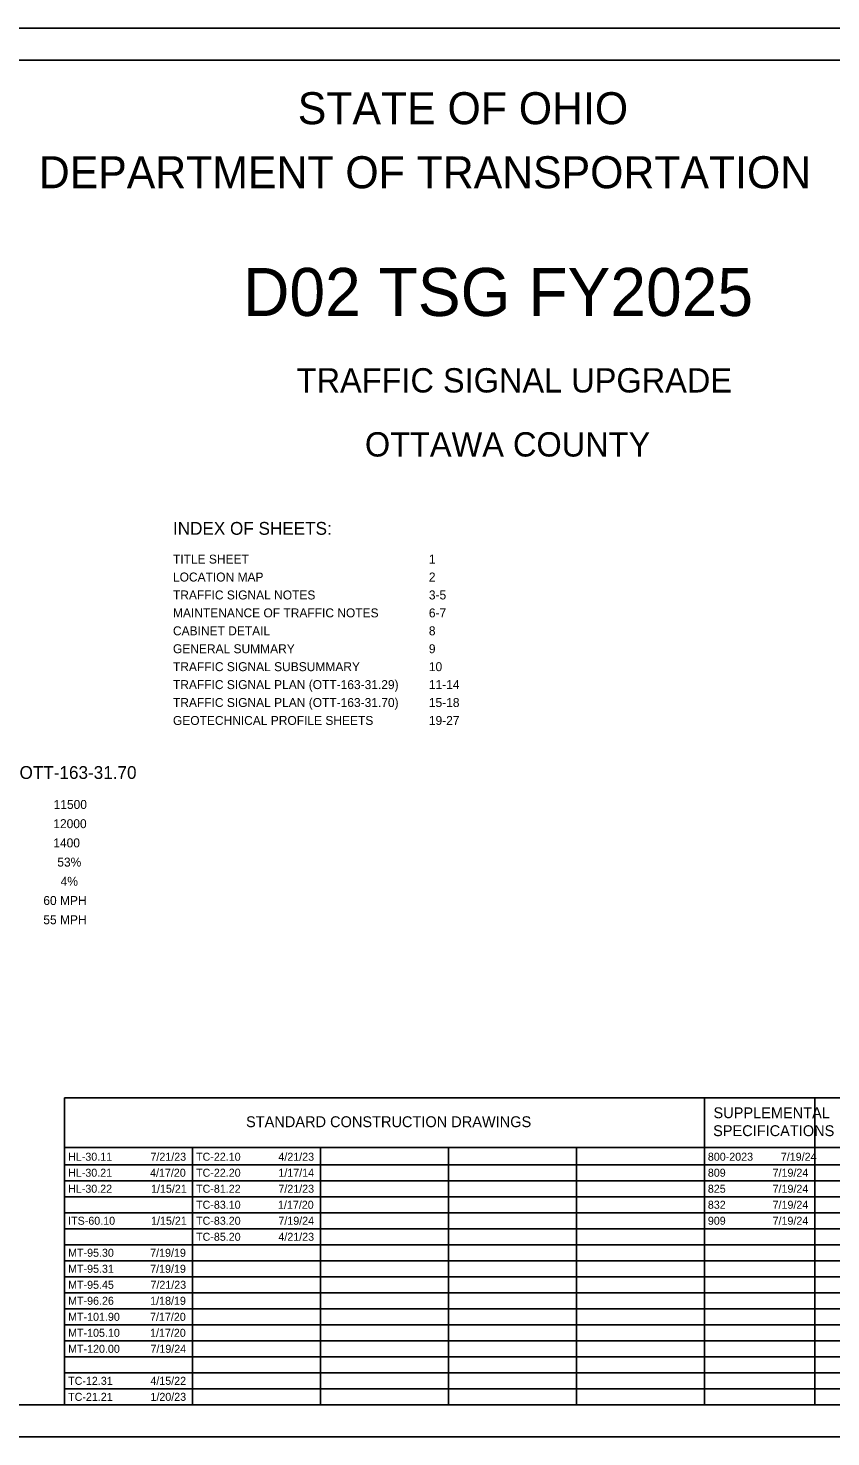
# Model space of a CAD drawing. Extents: x 0 to 34, y 0 to 22.
# Drawn here: x 9.58 to 22.13, y 0 to 22 of the extents above; entities that cross this region are included whole.
import ezdxf

# ---------------------------------------------------------------- set-up
doc = ezdxf.new("R2010")
doc.units = 0
for name, color, linetype in [('Default', 7, 'Continuous'), ('SH_Border', 7, 'Continuous'), ('SH_Cut_Line', 7, 'Continuous'), ('SH_Data', 7, 'Continuous'), ('SH_Text', 7, 'Continuous')]:
    doc.layers.add(name, color=color, linetype=linetype)

msp = doc.modelspace()

# ---------------------------------------------------------------- linework, layer by layer
at = {"layer": 'SH_Border'}
msp.add_lwpolyline([(1.5, 21.5), (33.5, 21.5), (33.5, 0.5), (1.5, 0.5)], close=True, dxfattribs=at)
at = {"layer": 'SH_Cut_Line'}
msp.add_lwpolyline([(0, 0), (34, 0), (34, 22), (0, 22)], close=True, dxfattribs=at)
at = {"layer": 'SH_Data'}
for p, q in [((10.15, 5.292), (23.6, 5.292)), ((10.15, 0.5), (10.15, 5.292)), ((20.15, 0.5), (20.15, 5.292)), ((21.875, 0.5), (21.875, 5.292)), ((10.15, 4.521), (23.6, 4.521)), ((12.15, 0.5), (12.15, 4.521)), ((14.15, 0.5), (14.15, 4.521)), ((16.15, 0.5), (16.15, 4.521)), ((18.15, 0.5), (18.15, 4.521)), ((10.15, 4.25), (23.6, 4.25)), ((10.15, 4), (23.6, 4)), ((10.15, 3.75), (23.6, 3.75)), ((10.15, 3.5), (23.6, 3.5)), ((10.15, 3.25), (23.6, 3.25)), ((10.15, 3), (23.6, 3)), ((10.15, 2.75), (23.6, 2.75)), ((10.15, 2.5), (23.6, 2.5)), ((10.15, 2.25), (23.6, 2.25)), ((10.15, 2), (23.6, 2)), ((10.15, 1.75), (23.6, 1.75)), ((10.15, 1.5), (23.6, 1.5)), ((10.15, 1.25), (23.6, 1.25)), ((10.15, 1), (23.6, 1)), ((10.15, 0.75), (23.6, 0.75))]:
    msp.add_line(p, q, dxfattribs=at)

# ---------------------------------------------------------------- texts
at = {"layer": 'Default'}
for s, p in [('HL-30.11', (10.205, 4.312)), ('7/21/23', (11.492, 4.312)), ('TC-22.10', (12.205, 4.312)), ('4/21/23', (13.492, 4.312)), ('800-2023', (20.205, 4.312)), ('7/19/24', (21.346, 4.312)), ('HL-30.21', (10.205, 4.062)), ('4/17/20', (11.486, 4.062)), ('TC-22.20', (12.205, 4.062)), ('1/17/14', (13.492, 4.062)), ('809', (20.205, 4.062)), ('7/19/24', (21.217, 4.062)), ('HL-30.22', (10.205, 3.812)), ('1/15/21', (11.502, 3.812)), ('TC-81.22', (12.205, 3.812)), ('7/21/23', (13.492, 3.812)), ('825', (20.205, 3.812)), ('7/19/24', (21.217, 3.812)), ('TC-83.10', (12.205, 3.562)), ('1/17/20', (13.486, 3.562)), ('832', (20.205, 3.562)), ('7/19/24', (21.217, 3.562)), ('ITS-60.10', (10.205, 3.312)), ('1/15/21', (11.502, 3.312)), ('TC-83.20', (12.205, 3.312)), ('7/19/24', (13.492, 3.312)), ('909', (20.205, 3.312)), ('7/19/24', (21.217, 3.312)), ('TC-85.20', (12.205, 3.062)), ('4/21/23', (13.492, 3.062)), ('MT-95.30', (10.205, 2.812)), ('7/19/19', (11.488, 2.812)), ('MT-95.31', (10.205, 2.562)), ('7/19/19', (11.488, 2.562)), ('MT-95.45', (10.205, 2.312)), ('7/21/23', (11.492, 2.312)), ('MT-96.26', (10.205, 2.062)), ('1/18/19', (11.488, 2.062)), ('MT-101.90', (10.205, 1.812)), ('7/17/20', (11.486, 1.812)), ('MT-105.10', (10.205, 1.562)), ('1/17/20', (11.486, 1.562)), ('MT-120.00', (10.205, 1.312)), ('7/19/24', (11.492, 1.312)), ('TC-12.31', (10.205, 0.812)), ('4/15/22', (11.491, 0.812)), ('TC-21.21', (10.205, 0.562)), ('1/20/23', (11.492, 0.562))]:
    msp.add_text(s, height=0.125, dxfattribs=at).set_placement(p)
at = {"layer": 'SH_Data'}
msp.add_text('DESIGN DESIGNATION                              OTT-163-31.29      OTT-163-31.70', height=0.2, dxfattribs=at).set_placement((2, 10.275))
at = {"layer": 'SH_Text'}
for s, height, p in [('STATE OF OHIO', 0.5, (13.795, 20.5)), ('DEPARTMENT OF TRANSPORTATION', 0.5, (9.747, 19.5)), ('D02 TSG FY2025', 0.75, (12.94, 17.505)), ('TRAFFIC SIGNAL UPGRADE', 0.38, (13.778, 16.31)), ('OTTAWA COUNTY', 0.38, (14.844, 15.31)), ('INDEX OF SHEETS:', 0.2, (11.844, 14.088)), ('TITLE SHEET', 0.14, (11.844, 13.638)), ('1', 0.14, (15.844, 13.638)), ('LOCATION MAP', 0.14, (11.844, 13.358)), ('2', 0.14, (15.844, 13.358)), ('TRAFFIC SIGNAL NOTES', 0.14, (11.844, 13.078)), ('3-5', 0.14, (15.844, 13.078)), ('MAINTENANCE OF TRAFFIC NOTES', 0.14, (11.844, 12.798)), ('6-7', 0.14, (15.844, 12.798)), ('CABINET DETAIL', 0.14, (11.844, 12.518)), ('8', 0.14, (15.844, 12.518)), ('GENERAL SUMMARY', 0.14, (11.844, 12.238)), ('9', 0.14, (15.844, 12.238)), ('TRAFFIC SIGNAL SUBSUMMARY', 0.14, (11.844, 11.958)), ('10', 0.14, (15.844, 11.958)), ('TRAFFIC SIGNAL PLAN (OTT-163-31.29)', 0.14, (11.844, 11.678)), ('11-14', 0.14, (15.844, 11.678)), ('TRAFFIC SIGNAL PLAN (OTT-163-31.70)', 0.14, (11.844, 11.398)), ('15-18', 0.14, (15.844, 11.398)), ('GEOTECHNICAL PROFILE SHEETS', 0.14, (11.844, 11.118)), ('19-27', 0.14, (15.844, 11.118)), ('8600                                   11500', 0.14, (7.742, 9.806)), ('9500                                   12000', 0.14, (7.737, 9.506)), ('1100                                   1400', 0.14, (7.737, 9.206)), ('52%                                     53%', 0.14, (7.737, 8.906)), ('3%                                        4%', 0.14, (7.737, 8.606)), ('60 MPH                           60 MPH', 0.14, (7.737, 8.306)), ('55 MPH                           55 MPH', 0.14, (7.737, 8.006)), ('SUPPLEMENTAL', 0.17, (20.293, 4.976)), ('STANDARD CONSTRUCTION DRAWINGS', 0.17, (12.986, 4.836)), ('SPECIFICATIONS', 0.17, (20.287, 4.696))]:
    msp.add_text(s, height=height, dxfattribs=at).set_placement(p)

doc.saveas('drawing.dxf')
